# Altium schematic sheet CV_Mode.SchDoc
size A3; SheetNumber: 2; SheetTotal: 4
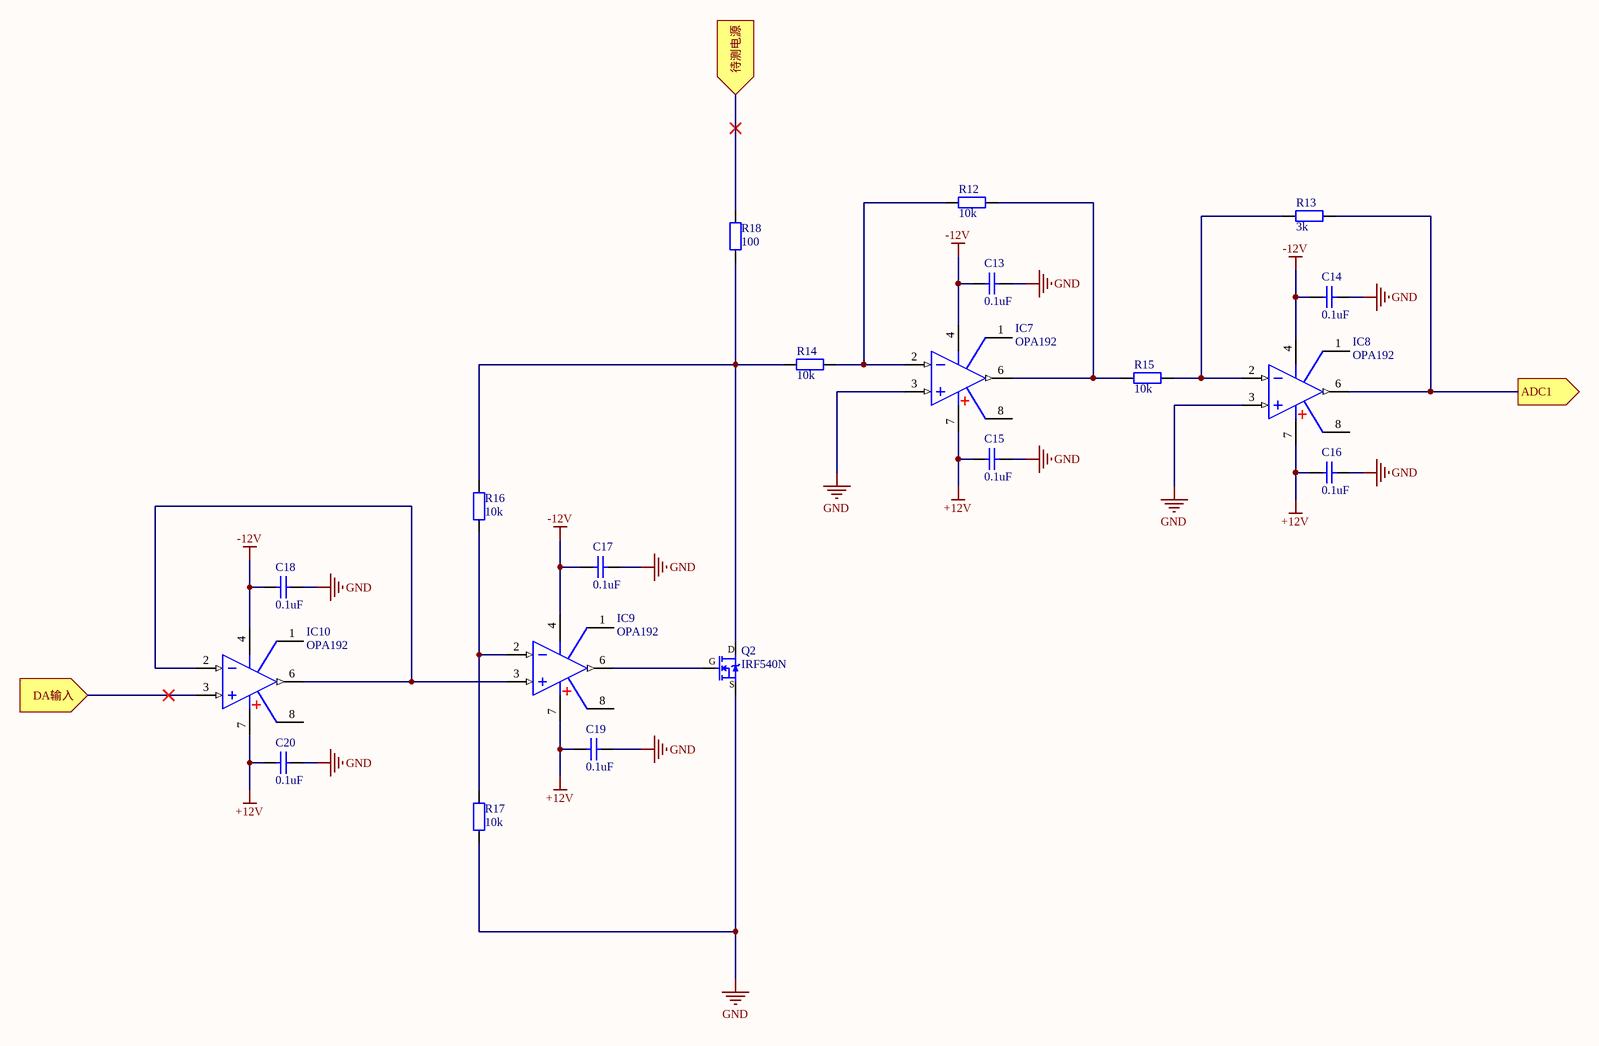
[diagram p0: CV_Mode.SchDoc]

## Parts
C13  0.1uF  [瓷片电容]
C14  0.1uF  [瓷片电容]
C15  0.1uF  [瓷片电容]
C16  0.1uF  [瓷片电容]
C17  0.1uF  [瓷片电容]
C18  0.1uF  [瓷片电容]
C19  0.1uF  [瓷片电容]
C20  0.1uF  [瓷片电容]
IC7  OPA192  [SOP8_N]
IC8  OPA192  [SOP8_N]
IC9  OPA192  [SOP8_N]
IC10  OPA192  [SOP8_N]
Q2  IRF540N  [TO263-3B]
R12  10k  [RS 1/4W]
R13  3k  [RS 1/4W]
R14  10k  [RS 1/4W]
R15  10k  [RS 1/4W]
R16  10k  [RS 1/4W]
R17  10k  [RS 1/4W]
R18  100  [RS 1/4W]

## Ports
ADC1 (out), DA输入 (in), 待测电源 (in)

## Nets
+12V: C15.1 C16.1 C19.1 C20.1 IC7.7(V+) IC8.7(V+) IC9.7(V+) IC10.7(V+)
-12V: C13.1 C14.1 C17.1 C18.1 IC7.4(V-) IC8.4(V-) IC9.4(V-) IC10.4(V-)
GND: C13.2 C14.2 C15.2 C16.2 C17.2 C18.2 C19.2 C20.2 IC7.3(IN+) IC8.3(IN+) Q2.3(D) R17.1
ADC1: IC8.6(OUT) R13.2 ; port ADC1
DA输入: IC10.3(IN+) ; port DA输入
待测电源: R18.2 ; port 待测电源
NetIC7_2: IC7.2(IN-) R12.1 R14.2
NetIC7_6: IC7.6(OUT) R12.2 R15.1
NetIC8_2: IC8.2(IN-) R13.1 R15.2
NetIC9_2: IC9.2(IN-) R16.1 R17.2
NetIC9_3: IC9.3(IN+) IC10.2(IN-) IC10.6(OUT)
NetIC9_6: IC9.6(OUT) Q2.1(G)
NetQ2_2: Q2.2(S) R14.1 R16.2 R18.1

Not connected (* = marked no-connect by the designer): IC7 1 8; IC8 1 8; IC9 1 8; IC10 1 8

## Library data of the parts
C13-C20 = Cap_DIP: 直插电容; Value: 100nF; Voltage: 63V
IC7-IC10 = OPA192: High-Voltage, Rail-to-Rail Input/Output, 5µV, 0.2µV/˚C, Precision Operational Amplifier; BOM名称: 单路精密运放; 版权归属: 源创客
Q2 = IRF540N: N沟场 100V/22A; BOM名称: 效应管; 版权归属: 源创客
R12-R18 = Res_DIP: 直插电阻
